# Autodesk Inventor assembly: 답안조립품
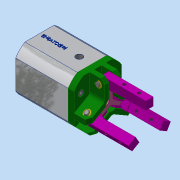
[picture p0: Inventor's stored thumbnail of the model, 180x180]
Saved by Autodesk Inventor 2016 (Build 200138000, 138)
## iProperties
Created: 2020-02
Part Number: 답안조립품
Document SubType Name: Assembly
Designer: Administrator
Author: Administrator
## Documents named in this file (13)
- C:\Users\Administrator\Desktop\700206V1004\답안조립품.iam
- C:\Users\Administrator\Desktop\700206V1004\본체.ipt
- C:\Users\Administrator\Desktop\700206V1004\본체헤드.ipt
- C:\Users\Administrator\Desktop\700206V1004\볼트 M4.ipt
- C:\Users\Administrator\Desktop\700206V1004\피스톤.ipt
- C:\Users\Administrator\Desktop\700206V1004\핀 A.ipt
- C:\Users\Administrator\Desktop\700206V1004\핀 B.ipt
- C:\Users\Administrator\Desktop\700206V1004\핑거.ipt
- C:\Users\Administrator\Desktop\700206V1004\E링.ipt
- C:\Users\Administrator\Desktop\700206V1004\O-RING 12x16.ipt
- C:\Users\Administrator\Desktop\700206V1004\O-RING 18x22.ipt
- C:\Users\Administrator\Desktop\700206V1004\O-RING 34x40.ipt
- C:\Users\Administrator\Desktop\700206V1004\로드.ipt
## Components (20 placed, 8 different names)
1. 피스톤:1
2. 핀 B:1 — 플러쉬:2
3. 핑거:1 — 플러쉬:3
4. E링:1
5. O-RING 12x16:1
6. O-RING 34x40:2
7. 핑거:2 — 플러쉬:2
8. 핑거:3 — 플러쉬:1
9. 핀 B:2 — 플러쉬:1
10. 핀 B:3 — 플러쉬:3
11. E링:2
12. 핀 A:3
13. E링:3
14. E링:4
15. 핀 A:4
16. E링:5
17. E링:6
18. 핀 A:5
19. O-RING 34x40:3
20. O-RING 18x22:1
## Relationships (3: Flush 3)
- 플러쉬:1 [Flush]: 핑거:3 ↔ 핀 B:2
- 플러쉬:2 [Flush]: 핀 B:1 ↔ 핑거:2
- 플러쉬:3 [Flush]: 핑거:1 ↔ 핀 B:3
## Named parameters: d21_d19 = 0, d22_d20 = 0, d23_d19 = 0, d24_d20 = 0
